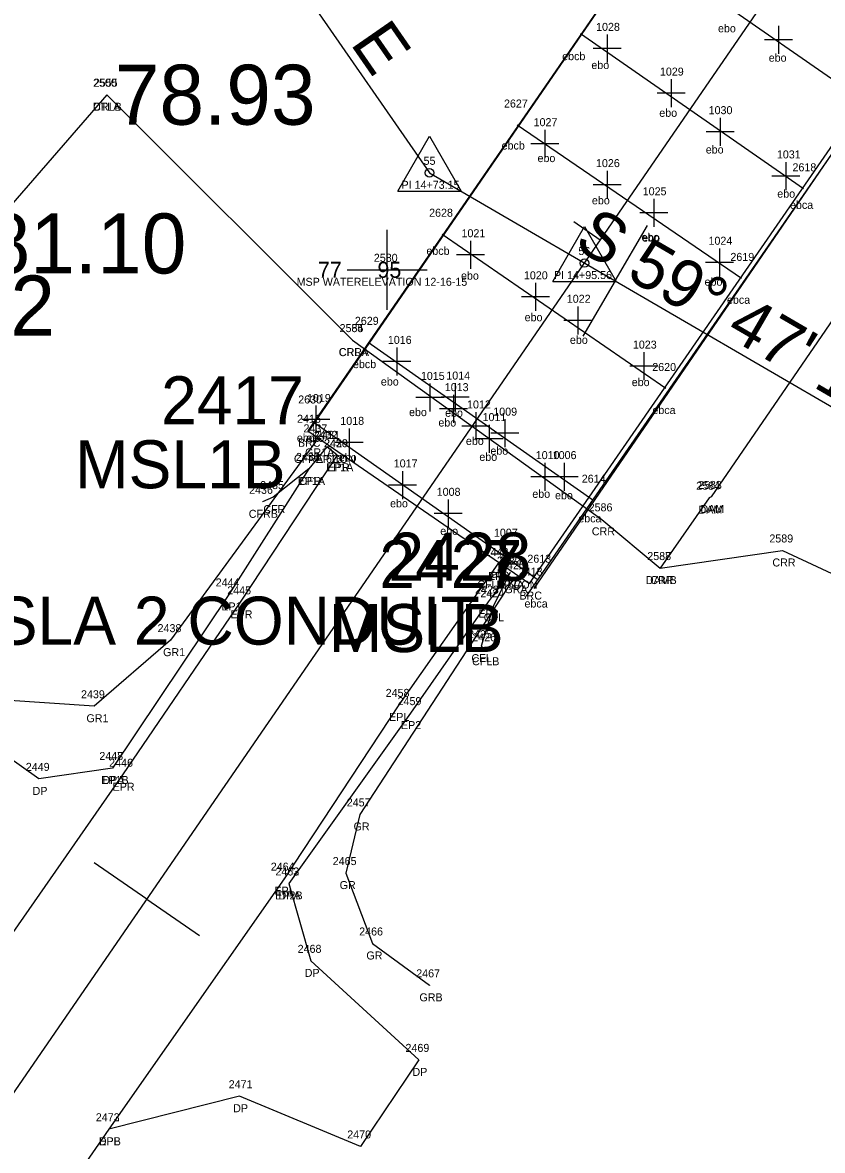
# Model space of a CAD drawing. Extents: x 2266664 to 2272542, y 716533 to 724777.
# Drawn here: x 2271022.9 to 2271122.9, y 722810 to 722951 of the extents above; entities that cross this region are included whole.
import ezdxf

# ---------------------------------------------------------------- set-up
doc = ezdxf.new("R2010")
doc.units = 0
for name, color, linetype in [('RD_EX_Bridge', 7, 'Continuous'), ('RD_EX_Bridge_txCode', 7, 'Continuous'), ('RD_EX_Conc', 7, 'Continuous'), ('RD_EX_Conc_txCode', 7, 'Continuous'), ('RD_EX_Dam', 7, 'Continuous'), ('RD_EX_Dam_txCode', 7, 'Continuous'), ('RD_EX_DR_Inlet_txCode', 7, 'Continuous'), ('RD_EX_Driveway', 7, 'Continuous'), ('RD_EX_Driveway_txCode', 7, 'Continuous'), ('RD_EX_GuardRail', 7, 'Continuous'), ('RD_EX_GuardRail_txCode', 7, 'Continuous'), ('RD_EX_H2O', 7, 'Continuous'), ('RD_EX_H2O_txCode', 7, 'Continuous'), ('RD_EX_Misc', 7, 'Continuous'), ('RD_EX_Misc_txCode', 7, 'Continuous'), ('RD_EX_Road', 7, 'Continuous'), ('RD_EX_Road_txCode', 7, 'Continuous'), ('RD_HC_Cl', 7, 'Continuous'), ('RD_HC_Data', 7, 'Continuous'), ('RD_HC_Data_Tic', 7, 'Continuous'), ('RD_HC_txCode', 7, 'Continuous'), ('RD_SMD_Locator', 7, 'Continuous')]:
    doc.layers.add(name, color=color, linetype=linetype)

msp = doc.modelspace()

# ---------------------------------------------------------------- linework, layer by layer
at = {"layer": 'RD_EX_Bridge'}
msp.add_lwpolyline([(2271154.4, 722979.52), (2271126.52, 722998.67), (2271058.56, 722899.96), (2271086.24, 722880.86), (2271154.4, 722979.52)], dxfattribs=at)
at = {"layer": 'RD_EX_Conc'}
for points in [[(2271060.91, 722897.95), (2271058.68, 722895.19), (2271054.21, 722891.67), (2271052.86, 722891.08)], [(2271083.82, 722882.24), (2271081.73, 722878.14), (2271080.19, 722873.04), (2271080.75, 722872.65)]]:
    msp.add_lwpolyline(points, dxfattribs=at)
at = {"layer": 'RD_EX_Dam'}
msp.add_lwpolyline([(2271152.21, 722956.41), (2271134.6, 722929.34), (2271126.04, 722916.39), (2271125.72, 722916.12), (2271108.94, 722891.69), (2271108.71, 722891.59), (2271102.6, 722882.8)], dxfattribs=at)
at = {"layer": 'RD_EX_Driveway'}
for points in [[(2271034.11, 722857.81), (2271024.92, 722856.45), (2271012.76, 722865.1), (2271006.76, 722871.86), (2270994.96, 722862.93), (2271003.93, 722846.02), (2271009.12, 722830.75), (2271009.25, 722819.48)], [(2271056.15, 722843.38), (2271058.93, 722833.71), (2271072.4, 722821.33), (2271065.14, 722810.51), (2271049.99, 722816.79), (2271033.67, 722812.66)]]:
    msp.add_lwpolyline(points, dxfattribs=at)
at = {"layer": 'RD_EX_GuardRail'}
for points in [[(2271059.63, 722898.76), (2271041.39, 722873.79), (2271031.82, 722865.53), (2271020.67, 722866.3), (2271015.7, 722870.29)], [(2271084.37, 722881.66), (2271065.04, 722852.01), (2271063.3, 722844.68), (2271066.64, 722835.88), (2271073.75, 722830.65)]]:
    msp.add_lwpolyline(points, dxfattribs=at)
at = {"layer": 'RD_EX_H2O'}
msp.add_line((2271064.14, 722911.29), (2271033.41, 722941.96), dxfattribs=at)
for points in [[(2271033.41, 722941.96), (2271017.26, 722923.37), (2271000.84, 722915.61), (2270984.69, 722924.7), (2270953.1, 722884.21), (2270916.86, 722756.99), (2270859.77, 722671.98), (2270798.36, 722591.12), (2270738.02, 722501.89), (2270682.59, 722424.89), (2270629.35, 722346.56), (2270572.53, 722262.27), (2270515.87, 722180.88), (2270459.66, 722106.47), (2270403.98, 722020.3), (2270343.58, 721932.89), (2270284.34, 721846.17), (2270230.48, 721766.75), (2270175.19, 721692.18), (2270115.51, 721607.69), (2270056.41, 721522.72), (2269992.94, 721435.27), (2269987.18, 721402.63)], [(2271064.14, 722911.29), (2271095.29, 722888.89), (2271102.6, 722882.8), (2271117.86, 722885), (2271133.88, 722877.53), (2271131.49, 722848.3), (2271161.12, 722800.68), (2271158.38, 722790.92), (2271209.97, 722733.05), (2271257.97, 722699.07), (2271328.71, 722663.53), (2271328.76, 722676.23), (2271359.03, 722679.94), (2271405.02, 722657.62), (2271442.98, 722642.77), (2271440.33, 722616.88), (2271427.19, 722613.92), (2271489.22, 722575.87)]]:
    msp.add_lwpolyline(points, dxfattribs=at)
at = {"layer": 'RD_EX_Misc'}
for p, q in [((2271126.58, 722998.7), (2271058.53, 722899.77)), ((2271155.61, 722980.33), (2271085.82, 722879.3)), ((2271086.83, 722880.23), (2271154.05, 722978.35)), ((2271128.04, 722941.14), (2271100.17, 722960.49)), ((2271120.49, 722930.19), (2271092.62, 722949.57)), ((2271117.37, 722950.57), (2271117.37, 722947.07)), ((2271095.95, 722949.49), (2271095.95, 722945.99)), ((2271119.12, 722948.82), (2271115.62, 722948.82)), ((2271097.7, 722947.74), (2271094.2, 722947.74)), ((2271103.94, 722943.9), (2271103.94, 722940.4)), ((2271105.69, 722942.15), (2271102.19, 722942.15)), ((2271110.06, 722939.08), (2271110.06, 722935.58)), ((2271112.73, 722918.99), (2271084.71, 722938.16)), ((2271088.15, 722937.58), (2271088.15, 722934.08)), ((2271111.81, 722937.33), (2271108.31, 722937.33)), ((2271089.9, 722935.83), (2271086.4, 722935.83)), ((2271118.27, 722933.55), (2271118.27, 722930.05)), ((2271095.96, 722932.46), (2271095.96, 722928.96)), ((2271120.02, 722931.8), (2271116.52, 722931.8)), ((2271097.71, 722930.71), (2271094.21, 722930.71)), ((2271101.78, 722928.94), (2271101.78, 722925.44)), ((2271103.53, 722927.19), (2271100.03, 722927.19)), ((2271068.46, 722915.08), (2271068.46, 722925.08)), ((2271103.28, 722905.23), (2271075.35, 722924.51)), ((2271078.86, 722923.7), (2271078.86, 722920.2)), ((2271110.01, 722922.76), (2271110.01, 722919.26)), ((2271080.61, 722921.95), (2271077.11, 722921.95)), ((2271063.46, 722920.08), (2271073.46, 722920.08)), ((2271111.76, 722921.01), (2271108.26, 722921.01)), ((2271086.98, 722918.44), (2271086.98, 722914.94)), ((2271088.73, 722916.69), (2271085.23, 722916.69)), ((2271092.29, 722915.51), (2271092.29, 722912.01)), ((2271094.04, 722913.76), (2271090.54, 722913.76)), ((2271094.15, 722891.27), (2271066.07, 722911)), ((2271069.66, 722910.37), (2271069.66, 722906.87)), ((2271100.55, 722909.78), (2271100.55, 722906.28)), ((2271071.41, 722908.62), (2271067.91, 722908.62)), ((2271102.3, 722908.03), (2271098.8, 722908.03)), ((2271073.77, 722905.87), (2271073.77, 722902.37)), ((2271076.95, 722905.91), (2271076.95, 722902.41)), ((2271076.76, 722904.46), (2271076.76, 722900.96)), ((2271059.53, 722903.1), (2271059.53, 722899.6)), ((2271075.52, 722904.12), (2271072.02, 722904.12)), ((2271078.7, 722904.16), (2271075.2, 722904.16)), ((2271078.51, 722902.71), (2271075.01, 722902.71)), ((2271079.54, 722902.3), (2271079.54, 722898.8)), ((2271061.28, 722901.35), (2271057.78, 722901.35)), ((2271087.35, 722881.27), (2271059.03, 722901.17)), ((2271063.7, 722900.25), (2271063.7, 722896.75)), ((2271081.29, 722900.55), (2271077.79, 722900.55)), ((2271081.19, 722900.72), (2271081.19, 722897.22)), ((2271083.15, 722901.4), (2271083.15, 722897.9)), ((2271082.94, 722898.97), (2271079.44, 722898.97)), ((2271084.9, 722899.65), (2271081.4, 722899.65)), ((2271065.45, 722898.5), (2271061.95, 722898.5)), ((2271090.6, 722895.97), (2271090.6, 722892.47)), ((2271070.38, 722894.93), (2271070.38, 722891.43)), ((2271088.17, 722895.97), (2271088.17, 722892.47)), ((2271072.13, 722893.18), (2271068.63, 722893.18)), ((2271089.92, 722894.22), (2271086.42, 722894.22)), ((2271092.35, 722894.22), (2271088.85, 722894.22)), ((2271076.08, 722891.38), (2271076.08, 722887.88)), ((2271077.83, 722889.63), (2271074.33, 722889.63)), ((2271083.22, 722886.27), (2271083.22, 722882.77)), ((2271084.97, 722884.52), (2271081.47, 722884.52))]:
    msp.add_line(p, q, dxfattribs=at)
at = {"layer": 'RD_EX_Road'}
msp.add_line((2271062.22, 722896.9), (2271060.91, 722897.95), dxfattribs=at)
for points in [[(2271062.22, 722896.9), (2271050.1, 722878.52), (2271035.36, 722856.97), (2271009.25, 722819.48), (2270948.68, 722732.14), (2270891.73, 722649.3), (2270830.29, 722559.72), (2270774.71, 722479.03), (2270718.54, 722397.26), (2270665.83, 722320.36), (2270608.79, 722237.92), (2270552.34, 722156.58), (2270498.7, 722078.55)], [(2271058.68, 722895.19), (2271048.65, 722879.5), (2271034.11, 722857.81)], [(2271082.27, 722883.31), (2271069.9, 722865.7), (2271055.57, 722843.98), (2271033.67, 722812.66), (2270967.43, 722716.72), (2270911.49, 722634.76), (2270850.44, 722546.34), (2270794.45, 722465.06), (2270738.33, 722383.22), (2270685.67, 722306.46), (2270626.75, 722221.55), (2270572.84, 722143.55), (2270518.64, 722064.54)], [(2271083.82, 722882.24), (2271081.07, 722878.6), (2271071.39, 722864.67), (2271056.15, 722843.38)]]:
    msp.add_lwpolyline(points, dxfattribs=at)
at = {"layer": 'RD_HC_Cl'}
for p, q in [((2267342.91, 717471.2), (2272360.46, 724762.59)), ((2271027.76, 722998.59), (2271073.75, 722932.2)), ((2271073.75, 722932.2), (2271155.58, 722884.55))]:
    msp.add_line(p, q, dxfattribs=at)
at = {"layer": 'RD_HC_Data'}
for p, q in [((2271069.78, 722929.91), (2271073.75, 722936.78)), ((2271073.75, 722936.78), (2271077.72, 722929.91)), ((2271069.78, 722929.91), (2271077.72, 722929.91)), ((2271089.15, 722918.63), (2271093.12, 722925.51)), ((2271093.12, 722925.51), (2271097.09, 722918.63)), ((2271089.15, 722918.63), (2271097.09, 722918.63))]:
    msp.add_line(p, q, dxfattribs=at)
for centre in [(2271073.75, 722932.2), (2271093.12, 722920.92)]:
    msp.add_circle(centre, 0.529, dxfattribs=at)
at = {"layer": 'RD_HC_Data_Tic'}
for p, q in [((2271095.1, 722923.79), (2271091.8, 722926.06)), ((2271096.95, 722918.69), (2271100.98, 722925.6)), ((2271096.95, 722918.69), (2271092.93, 722911.77)), ((2271038.41, 722841.41), (2271031.82, 722845.95)), ((2271038.41, 722841.41), (2271045, 722836.88))]:
    msp.add_line(p, q, dxfattribs=at)
at = {"layer": 'RD_SMD_Locator'}
for centre in [(2271033.41, 722941.96), (2271033.41, 722941.96), (2271073.75, 722932.2), (2271093.12, 722920.92), (2271064.14, 722911.29), (2271064.14, 722911.29), (2271058.53, 722899.77), (2271058.56, 722899.96), (2271059.63, 722898.76), (2271060.91, 722897.95), (2271060.91, 722897.95), (2271062.22, 722896.9), (2271062.22, 722896.9), (2271058.68, 722895.19), (2271058.68, 722895.19), (2271052.86, 722891.08), (2271054.21, 722891.67), (2271108.71, 722891.59), (2271108.94, 722891.69), (2271095.29, 722888.89), (2271117.86, 722885), (2271082.27, 722883.31), (2271083.82, 722882.24), (2271083.82, 722882.24), (2271102.6, 722882.8), (2271102.6, 722882.8), (2271084.37, 722881.66), (2271086.24, 722880.86), (2271048.65, 722879.5), (2271085.82, 722879.3), (2271086.83, 722880.23), (2271050.1, 722878.52), (2271081.07, 722878.6), (2271081.73, 722878.14), (2271041.39, 722873.79), (2271080.19, 722873.04), (2271080.75, 722872.65), (2271031.82, 722865.53), (2271069.9, 722865.7), (2271071.39, 722864.67), (2271034.11, 722857.81), (2271034.11, 722857.81), (2271035.36, 722856.97), (2271024.92, 722856.45), (2271065.04, 722852.01), (2271055.57, 722843.98), (2271063.3, 722844.68), (2271056.15, 722843.38), (2271056.15, 722843.38), (2271066.64, 722835.88), (2271058.93, 722833.71), (2271073.75, 722830.65), (2271072.4, 722821.33), (2271049.99, 722816.79), (2271033.67, 722812.66), (2271033.67, 722812.66), (2271065.14, 722810.51)]:
    msp.add_circle(centre, 0.001, dxfattribs=at)

# ---------------------------------------------------------------- texts
at = {"layer": 'RD_EX_Bridge_txCode'}
for s, p in [('2416', (2271057.19, 722900.96)), ('BRC', (2271057.31, 722897.96)), ('2418', (2271084.9, 722881.86)), ('BRC', (2271084.99, 722878.86))]:
    msp.add_text(s, height=1, dxfattribs=at).set_placement(p)
at = {"layer": 'RD_EX_Conc_txCode'}
for s, p in [('2432', (2271059.28, 722898.95)), ('CFRA 6CON', (2271056.8, 722895.95)), ('2433', (2271057.05, 722896.19)), ('2435', (2271052.58, 722892.67)), ('CFR', (2271057.45, 722893.19)), ('2436', (2271051.2, 722892.08)), ('CFR', (2271052.98, 722889.67)), ('CFRB', (2271051.16, 722889.08)), ('2422', (2271082.19, 722883.24)), ('CFLA 6CON', (2271079.73, 722880.24)), ('2424', (2271080.1, 722879.14)), ('CFL', (2271080.53, 722876.14)), ('2425', (2271078.56, 722874.04)), ('2426', (2271079.09, 722873.65)), ('CFL', (2271078.99, 722871.04)), ('CFLB', (2271079.07, 722870.65))]:
    msp.add_text(s, height=1, dxfattribs=at).set_placement(p)
at = {"layer": 'RD_EX_Dam_txCode'}
for s, p in [('2584', (2271107.08, 722892.59)), ('2583', (2271107.31, 722892.69)), ('DAM', (2271107.38, 722889.59)), ('DAM', (2271107.61, 722889.69)), ('2587', (2271100.97, 722883.8)), ('DAMB', (2271100.79, 722880.8))]:
    msp.add_text(s, height=1, dxfattribs=at).set_placement(p)
at = {"layer": 'RD_EX_DR_Inlet_txCode'}
for s, p in [('78.93', (2271034.41, 722938.21)), ('81.10', (2271018.26, 722919.62)), ('81.02', (2271001.84, 722911.86))]:
    msp.add_text(s, height=7.5, dxfattribs=at).set_placement(p)
at = {"layer": 'RD_EX_Driveway_txCode'}
for s, p in [('2448', (2271032.48, 722858.81)), ('2449', (2271023.29, 722857.45)), ('DPA', (2271032.85, 722855.81)), ('DP', (2271024.14, 722854.45)), ('2463', (2271054.49, 722844.38)), ('DPA', (2271054.88, 722841.38)), ('2468', (2271057.27, 722834.71)), ('DP', (2271058.15, 722831.71)), ('2469', (2271070.75, 722822.33)), ('DP', (2271071.62, 722819.33)), ('2471', (2271048.65, 722817.79)), ('DP', (2271049.21, 722814.79)), ('2472', (2271032.04, 722813.66)), ('DPB', (2271032.42, 722810.66)), ('2470', (2271063.47, 722811.51))]:
    msp.add_text(s, height=1, dxfattribs=at).set_placement(p)
at = {"layer": 'RD_EX_GuardRail_txCode'}
for s, p in [('2437', (2271058, 722899.76)), ('GR1A', (2271058.2, 722896.76)), ('2420', (2271082.7, 722882.66)), ('GRA', (2271083.11, 722879.66)), ('2438', (2271039.76, 722874.79)), ('GR1', (2271040.45, 722871.79)), ('2439', (2271030.19, 722866.53)), ('GR1', (2271030.87, 722863.53)), ('2457', (2271063.41, 722853.01)), ('GR', (2271064.26, 722850.01)), ('2465', (2271061.65, 722845.68)), ('GR', (2271062.52, 722842.68)), ('2466', (2271064.96, 722836.88)), ('GR', (2271065.86, 722833.88)), ('2467', (2271072.09, 722831.65)), ('GRB', (2271072.49, 722828.65))]:
    msp.add_text(s, height=1, dxfattribs=at).set_placement(p)
at = {"layer": 'RD_EX_H2O_txCode'}
for s, p in [('2500', (2271031.7, 722942.96)), ('2555', (2271031.78, 722942.96)), ('CRLB', (2271031.71, 722939.96)), ('DTLA', (2271031.68, 722939.96)), ('2554', (2271062.51, 722912.29)), ('2585', (2271062.51, 722912.29)), ('CRRA', (2271062.4, 722909.29)), ('CRLA', (2271062.43, 722909.29)), ('2586', (2271093.64, 722889.89)), ('CRR', (2271094.04, 722886.89)), ('2589', (2271116.23, 722886)), ('2588', (2271100.97, 722883.8)), ('CRR', (2271116.61, 722883)), ('CRR', (2271101.34, 722880.8))]:
    msp.add_text(s, height=1, dxfattribs=at).set_placement(p)
at = {"layer": 'RD_EX_Misc_txCode'}
for s, height, p in [('1028', 1, (2271094.57, 722949.94)), ('ebo', 1, (2271109.81, 722949.76)), ('ebcb', 1, (2271090.33, 722946.28)), ('ebo', 1, (2271116.15, 722946.09)), ('ebo', 1, (2271093.98, 722945.17)), ('1029', 1, (2271102.55, 722944.35)), ('2627', 1, (2271083.06, 722940.36)), ('ebo', 1, (2271102.47, 722939.2)), ('1030', 1, (2271108.64, 722939.53)), ('1027', 1, (2271086.76, 722938.03)), ('ebcb', 1, (2271082.76, 722935.11)), ('ebo', 1, (2271108.28, 722934.61)), ('ebo', 1, (2271087.25, 722933.54)), ('1031', 1, (2271117.17, 722934)), ('1026', 1, (2271094.56, 722932.91)), ('2618', 1, (2271119.12, 722932.39)), ('1025', 1, (2271100.4, 722929.39)), ('ebo', 1, (2271117.22, 722929.1)), ('ebo', 1, (2271094.05, 722928.26)), ('ebca', 1, (2271118.81, 722927.69)), ('2628', 1, (2271073.7, 722926.71)), ('1021', 1, (2271077.75, 722924.15)), ('ebo', 1, (2271100.25, 722923.67)), ('ebo', 1, (2271100.33, 722923.59)), ('1024', 1, (2271108.62, 722923.21)), ('ebcb', 1, (2271073.36, 722921.95)), ('2580', 1, (2271066.79, 722921.08)), ('2619', 1, (2271111.36, 722921.19)), ('77      95', 2, (2271059.81, 722919.08)), ('MSP WATERELEVATION 12-16-15', 1, (2271057.14, 722918.08)), ('ebo', 1, (2271077.69, 722918.85)), ('1020', 1, (2271085.55, 722918.89)), ('ebo', 1, (2271108.13, 722918.09)), ('1022', 1, (2271090.91, 722915.96)), ('ebca', 1, (2271110.93, 722915.83)), ('ebo', 1, (2271085.64, 722913.65)), ('2629', 1, (2271064.42, 722913.2)), ('1016', 1, (2271068.54, 722910.82)), ('ebo', 1, (2271091.3, 722910.82)), ('1023', 1, (2271099.17, 722910.23)), ('ebcb', 1, (2271064.18, 722907.79)), ('1015', 1, (2271072.67, 722906.32)), ('1014', 1, (2271075.85, 722906.36)), ('2620', 1, (2271101.59, 722907.43)), ('2417', 6, (2271040.2, 722900.77)), ('ebo', 1, (2271067.67, 722905.61)), ('1013', 1, (2271075.66, 722904.91)), ('ebo', 1, (2271099.03, 722905.54)), ('1019', 1, (2271058.43, 722903.55)), ('2630', 1, (2271057.34, 722903.37)), ('1012', 1, (2271078.44, 722902.75)), ('ebca', 1, (2271101.61, 722902.05)), ('1018', 1, (2271062.6, 722900.7)), ('ebo', 1, (2271071.19, 722901.79)), ('ebo', 1, (2271075.7, 722901.71)), ('1011', 1, (2271080.38, 722901.17)), ('1009', 1, (2271081.72, 722901.85)), ('ebo', 1, (2271074.86, 722900.49)), ('MSL1B', 6, (2271029.45, 722892.77)), ('ebcb', 1, (2271057.17, 722898.58)), ('ebo', 1, (2271058.34, 722898.57)), ('ebo', 1, (2271078.3, 722898.19)), ('ebo', 1, (2271081.36, 722896.97)), ('1010', 1, (2271087.03, 722896.42)), ('1006', 1, (2271089.15, 722896.42)), ('ebo', 1, (2271062.4, 722896.13)), ('1017', 1, (2271069.28, 722895.38)), ('ebo', 1, (2271079.98, 722896.2)), ('2614', 1, (2271092.78, 722893.47)), ('1008', 1, (2271074.65, 722891.83)), ('ebo', 1, (2271086.6, 722891.58)), ('ebo', 1, (2271089.44, 722891.4)), ('ebo', 1, (2271068.82, 722890.39)), ('ebca', 1, (2271092.35, 722888.51)), ('ebo', 1, (2271075.09, 722886.94)), ('1007', 1, (2271081.8, 722886.72)), ('2427', 6, (2271067.48, 722880.3)), ('2428', 6, (2271068.61, 722881.23)), ('2613', 1, (2271085.98, 722883.47)), ('ebo', 1, (2271081.45, 722881.57)), ('MSLA 2 CONDUIT', 6, (2271012.72, 722873.23)), ('MSLB', 6, (2271061.17, 722872.3)), ('ebca', 1, (2271085.62, 722877.87))]:
    msp.add_text(s, height=height, dxfattribs=at).set_placement(p)
at = {"layer": 'RD_EX_Road_txCode'}
for s, p in [('2431', (2271059.57, 722898.95)), ('2430', (2271060.55, 722897.9)), ('2429', (2271060.59, 722897.9)), ('2434', (2271057.05, 722896.19)), ('EP1B', (2271059.52, 722895.95)), ('EP1A', (2271060.81, 722894.9)), ('EPR', (2271060.99, 722894.9)), ('EP1A', (2271057.27, 722893.19)), ('2443', (2271080.64, 722884.31)), ('2421', (2271082.47, 722883.24)), ('EPL', (2271081.07, 722881.31)), ('2444', (2271047.02, 722880.5)), ('2445', (2271048.47, 722879.52)), ('2423', (2271079.44, 722879.6)), ('EP2A', (2271082.13, 722880.24)), ('EP1', (2271047.73, 722877.5)), ('EPR', (2271048.87, 722876.52)), ('EP2', (2271079.86, 722876.6)), ('2458', (2271068.27, 722866.7)), ('2459', (2271069.76, 722865.67)), ('EPL', (2271068.7, 722863.7)), ('EP2', (2271070.18, 722862.67)), ('2447', (2271032.48, 722858.81)), ('2446', (2271033.71, 722857.97)), ('EP1B', (2271032.72, 722855.81)), ('EPR', (2271034.14, 722854.97)), ('2464', (2271053.91, 722844.98)), ('2462', (2271054.49, 722844.38)), ('EPL', (2271054.36, 722841.98)), ('EP2B', (2271054.47, 722841.38)), ('2473', (2271032.04, 722813.66)), ('EPL', (2271032.47, 722810.66))]:
    msp.add_text(s, height=1, dxfattribs=at).set_placement(p)
at = {"layer": 'RD_HC_Data'}
for s, rotation, p in [('S 34%%d 42\' 35" E', 304.7097, (2271036.06, 722988.36)), ('S 59%%d 47\' 19" E', 329.7887, (2271091.63, 722922.94))]:
    msp.add_text(s, height=6, rotation=rotation, dxfattribs=at).set_placement(p)
at = {"layer": 'RD_HC_txCode'}
for s, p in [('55', (2271073.01, 722933.2)), ('PI 14+73.15', (2271070.25, 722930.2)), ('56', (2271092.36, 722921.92)), ('PI 14+95.56', (2271089.31, 722918.92))]:
    msp.add_text(s, height=1, dxfattribs=at).set_placement(p)

doc.saveas('drawing.dxf')
